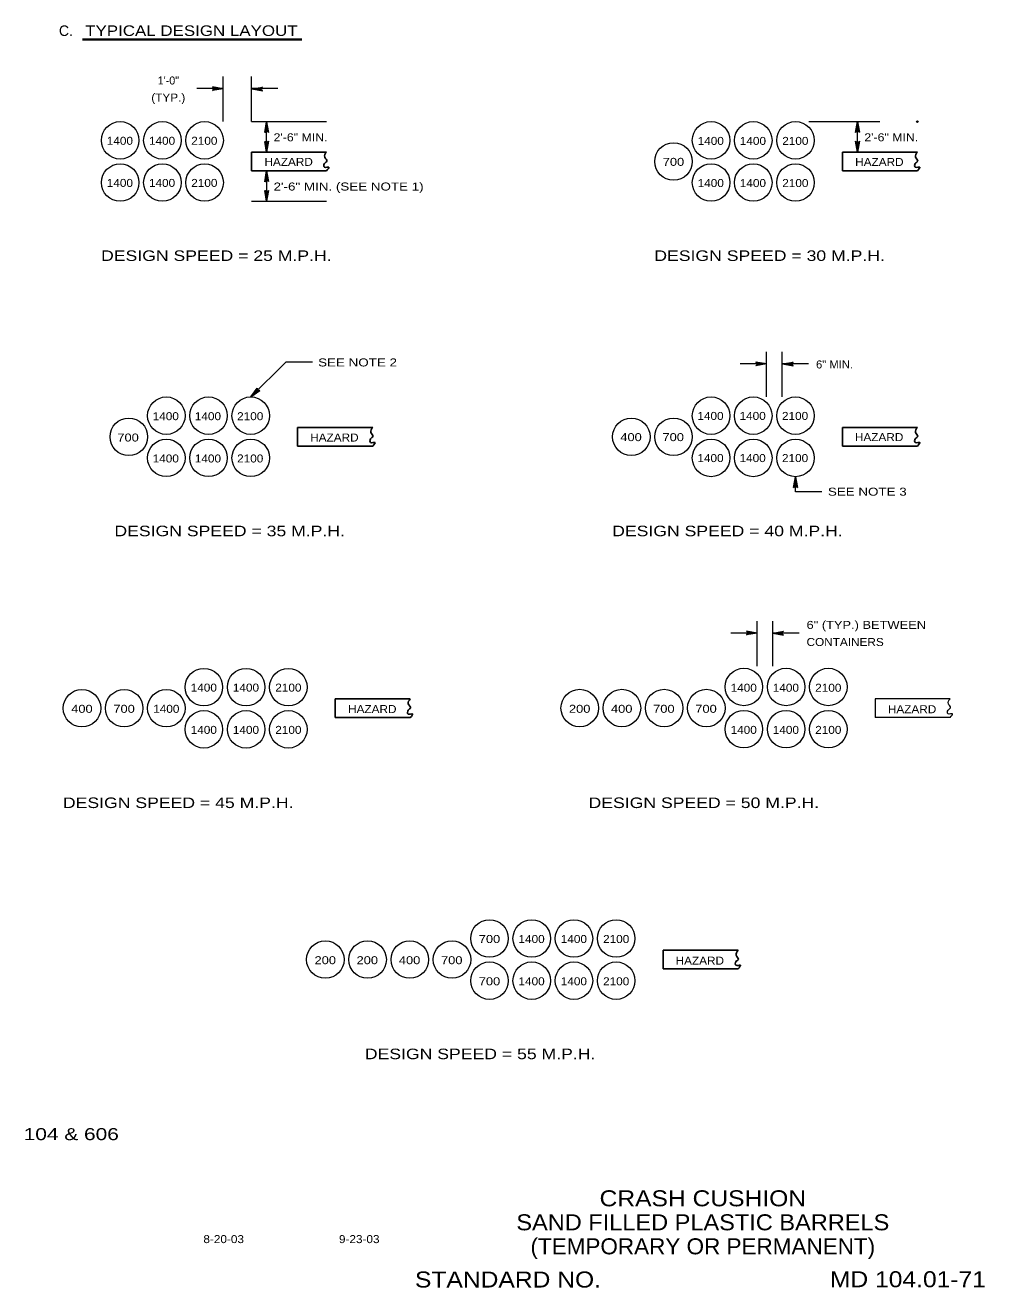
# Model space of a CAD drawing. Extents: x 2147606.19 to 2147613.38, y 2147556.61 to 2147566.08.
import ezdxf
from ezdxf.enums import TextEntityAlignment as Align

# ---------------------------------------------------------------- set-up
doc = ezdxf.new("R2010")
doc.units = 0
doc.header["$LTSCALE"] = 0.024
doc.header["$PDMODE"] = 32
doc.header["$PDSIZE"] = 0.012
for name, color, linetype, lineweight in [('1', 7, 'Continuous', 25), ('10', 7, 'Continuous', 13), ('12', 7, 'Continuous', 13)]:
    doc.layers.add(name, color=color, linetype=linetype, lineweight=lineweight)
doc.layers.add('13', color=7, linetype='Continuous')

msp = doc.modelspace()

# ---------------------------------------------------------------- hatches: boundary and pattern name
at = {"layer": '10'}
for points in [[(2147607.589, 2147565.616), (2147607.67, 2147565.601), (2147607.589, 2147565.587), (2147607.604, 2147565.601)], [(2147607.964, 2147565.586), (2147607.883, 2147565.601), (2147607.964, 2147565.614), (2147607.947, 2147565.601)], [(2147607.981, 2147565.273), (2147607.995, 2147565.354), (2147608.009, 2147565.274), (2147607.995, 2147565.288)], [(2147612.41, 2147565.274), (2147612.424, 2147565.355), (2147612.438, 2147565.275), (2147612.424, 2147565.289)], [(2147608.01, 2147565.207), (2147607.995, 2147565.126), (2147607.982, 2147565.206), (2147607.995, 2147565.191)], [(2147612.438, 2147565.208), (2147612.424, 2147565.126), (2147612.41, 2147565.207), (2147612.424, 2147565.192)], [(2147607.981, 2147564.904), (2147607.995, 2147564.985), (2147608.009, 2147564.905), (2147607.995, 2147564.92)], [(2147608.01, 2147564.838), (2147607.995, 2147564.757), (2147607.982, 2147564.837), (2147607.995, 2147564.822)], [(2147611.661, 2147563.552), (2147611.742, 2147563.538), (2147611.661, 2147563.524), (2147611.676, 2147563.538)], [(2147611.941, 2147563.523), (2147611.86, 2147563.538), (2147611.941, 2147563.552), (2147611.924, 2147563.538)], [(2147607.944, 2147563.338), (2147607.876, 2147563.29), (2147607.924, 2147563.357), (2147607.923, 2147563.337)], [(2147611.945, 2147562.611), (2147611.96, 2147562.692), (2147611.973, 2147562.611), (2147611.96, 2147562.625)], [(2147611.591, 2147561.534), (2147611.672, 2147561.519), (2147611.591, 2147561.506), (2147611.606, 2147561.519)], [(2147611.87, 2147561.504), (2147611.79, 2147561.519), (2147611.87, 2147561.533), (2147611.854, 2147561.519)]]:
    msp.add_hatch(color=256, dxfattribs=at).paths.add_polyline_path(points)

# ---------------------------------------------------------------- linework, layer by layer
at = {"layer": '1'}
for p, q in [((2147608.444, 2147565.126), (2147607.882, 2147565.126)), ((2147607.882, 2147565.126), (2147607.882, 2147564.986)), ((2147612.873, 2147565.126), (2147612.311, 2147565.126)), ((2147612.311, 2147565.126), (2147612.311, 2147564.986)), ((2147608.444, 2147564.986), (2147607.882, 2147564.986)), ((2147612.873, 2147564.986), (2147612.311, 2147564.986)), ((2147608.79, 2147563.062), (2147608.227, 2147563.062)), ((2147608.227, 2147563.062), (2147608.227, 2147562.921)), ((2147612.873, 2147563.062), (2147612.311, 2147563.062)), ((2147612.311, 2147563.062), (2147612.311, 2147562.921)), ((2147608.79, 2147562.921), (2147608.227, 2147562.921)), ((2147612.873, 2147562.921), (2147612.311, 2147562.921)), ((2147609.072, 2147561.027), (2147608.509, 2147561.027)), ((2147608.509, 2147561.027), (2147608.509, 2147560.886)), ((2147609.072, 2147560.886), (2147608.509, 2147560.886)), ((2147611.529, 2147559.142), (2147610.967, 2147559.142)), ((2147610.967, 2147559.142), (2147610.967, 2147559.002)), ((2147611.529, 2147559.002), (2147610.967, 2147559.002))]:
    msp.add_line(p, q, dxfattribs=at)
for points in [[(2147608.444, 2147564.986), (2147608.461, 2147565.013), (2147608.428, 2147565.013), (2147608.428, 2147565.041), (2147608.446, 2147565.058), (2147608.43, 2147565.089), (2147608.444, 2147565.126)], [(2147612.873, 2147564.986), (2147612.89, 2147565.013), (2147612.857, 2147565.013), (2147612.857, 2147565.041), (2147612.875, 2147565.058), (2147612.859, 2147565.089), (2147612.873, 2147565.126)], [(2147608.79, 2147562.921), (2147608.807, 2147562.949), (2147608.774, 2147562.949), (2147608.774, 2147562.976), (2147608.792, 2147562.994), (2147608.776, 2147563.024), (2147608.79, 2147563.062)], [(2147612.873, 2147562.921), (2147612.89, 2147562.949), (2147612.857, 2147562.949), (2147612.857, 2147562.976), (2147612.875, 2147562.994), (2147612.859, 2147563.024), (2147612.873, 2147563.062)], [(2147609.072, 2147560.886), (2147609.089, 2147560.913), (2147609.056, 2147560.913), (2147609.056, 2147560.941), (2147609.074, 2147560.959), (2147609.057, 2147560.989), (2147609.072, 2147561.027)], [(2147611.529, 2147559.002), (2147611.546, 2147559.029), (2147611.513, 2147559.029), (2147611.513, 2147559.056), (2147611.531, 2147559.074), (2147611.515, 2147559.104), (2147611.529, 2147559.142)]]:
    msp.add_spline(points, degree=3, dxfattribs=at)
at = {"layer": '10'}
for p, q in [((2147607.67, 2147565.355), (2147607.67, 2147565.692)), ((2147607.882, 2147565.355), (2147607.882, 2147565.692)), ((2147607.67, 2147565.602), (2147607.473, 2147565.602)), ((2147607.67, 2147565.601), (2147607.589, 2147565.616)), ((2147607.67, 2147565.601), (2147607.589, 2147565.587)), ((2147608.079, 2147565.603), (2147607.882, 2147565.603)), ((2147607.883, 2147565.601), (2147607.964, 2147565.614)), ((2147607.883, 2147565.601), (2147607.964, 2147565.586)), ((2147607.882, 2147565.355), (2147608.444, 2147565.355)), ((2147607.995, 2147565.354), (2147607.981, 2147565.273)), ((2147607.994, 2147565.126), (2147607.994, 2147565.355)), ((2147607.995, 2147565.354), (2147608.009, 2147565.274)), ((2147611.959, 2147565.355), (2147611.96, 2147565.355)), ((2147612.059, 2147565.355), (2147612.592, 2147565.355)), ((2147612.424, 2147565.355), (2147612.41, 2147565.274)), ((2147612.424, 2147565.355), (2147612.438, 2147565.275)), ((2147612.424, 2147565.127), (2147612.424, 2147565.355)), ((2147607.995, 2147565.126), (2147607.982, 2147565.206)), ((2147607.995, 2147565.126), (2147608.01, 2147565.207)), ((2147612.424, 2147565.126), (2147612.41, 2147565.207)), ((2147612.424, 2147565.126), (2147612.438, 2147565.208)), ((2147607.995, 2147564.985), (2147607.981, 2147564.904)), ((2147607.994, 2147564.986), (2147607.994, 2147564.757)), ((2147607.995, 2147564.985), (2147608.009, 2147564.905)), ((2147607.995, 2147564.757), (2147607.982, 2147564.837)), ((2147607.995, 2147564.757), (2147608.01, 2147564.838)), ((2147607.882, 2147564.757), (2147608.444, 2147564.757)), ((2147611.742, 2147563.29), (2147611.742, 2147563.628)), ((2147611.86, 2147563.29), (2147611.86, 2147563.628)), ((2147608.139, 2147563.552), (2147607.877, 2147563.29)), ((2147608.338, 2147563.552), (2147608.139, 2147563.552)), ((2147611.742, 2147563.538), (2147611.545, 2147563.538)), ((2147611.742, 2147563.538), (2147611.661, 2147563.552)), ((2147611.742, 2147563.538), (2147611.661, 2147563.524)), ((2147611.86, 2147563.538), (2147611.941, 2147563.552)), ((2147611.86, 2147563.538), (2147611.941, 2147563.523)), ((2147612.057, 2147563.538), (2147611.86, 2147563.538)), ((2147607.876, 2147563.29), (2147607.924, 2147563.357)), ((2147607.876, 2147563.29), (2147607.944, 2147563.338)), ((2147611.96, 2147562.692), (2147611.945, 2147562.611)), ((2147611.959, 2147562.58), (2147611.959, 2147562.693)), ((2147611.96, 2147562.692), (2147611.973, 2147562.611)), ((2147612.157, 2147562.58), (2147611.96, 2147562.58)), ((2147611.672, 2147561.272), (2147611.672, 2147561.609)), ((2147611.789, 2147561.272), (2147611.789, 2147561.609)), ((2147611.672, 2147561.519), (2147611.474, 2147561.519)), ((2147611.672, 2147561.519), (2147611.591, 2147561.534)), ((2147611.672, 2147561.519), (2147611.591, 2147561.506)), ((2147611.79, 2147561.519), (2147611.87, 2147561.533)), ((2147611.79, 2147561.519), (2147611.87, 2147561.504)), ((2147611.987, 2147561.519), (2147611.79, 2147561.519))]:
    msp.add_line(p, q, dxfattribs=at)
for points in [[(2147607.589, 2147565.616), (2147607.604, 2147565.601), (2147607.589, 2147565.587)], [(2147607.964, 2147565.586), (2147607.947, 2147565.601), (2147607.964, 2147565.614)], [(2147607.981, 2147565.273), (2147607.995, 2147565.288), (2147608.009, 2147565.274)], [(2147612.41, 2147565.274), (2147612.424, 2147565.289), (2147612.438, 2147565.275)], [(2147608.01, 2147565.207), (2147607.995, 2147565.191), (2147607.982, 2147565.206)], [(2147612.438, 2147565.208), (2147612.424, 2147565.192), (2147612.41, 2147565.207)], [(2147607.981, 2147564.904), (2147607.995, 2147564.92), (2147608.009, 2147564.905)], [(2147608.01, 2147564.838), (2147607.995, 2147564.822), (2147607.982, 2147564.837)], [(2147611.661, 2147563.552), (2147611.676, 2147563.538), (2147611.661, 2147563.524)], [(2147611.941, 2147563.523), (2147611.924, 2147563.538), (2147611.941, 2147563.552)], [(2147607.944, 2147563.338), (2147607.923, 2147563.337), (2147607.924, 2147563.357)], [(2147611.945, 2147562.611), (2147611.96, 2147562.625), (2147611.973, 2147562.611)], [(2147611.591, 2147561.534), (2147611.606, 2147561.519), (2147611.591, 2147561.506)], [(2147611.87, 2147561.504), (2147611.854, 2147561.519), (2147611.87, 2147561.533)]]:
    msp.add_lwpolyline(points, dxfattribs=at)
for points in [[(2147607.589, 2147565.616), (2147607.67, 2147565.601), (2147607.589, 2147565.587), (2147607.604, 2147565.601)], [(2147607.964, 2147565.586), (2147607.883, 2147565.601), (2147607.964, 2147565.614), (2147607.947, 2147565.601)], [(2147607.981, 2147565.273), (2147607.995, 2147565.354), (2147608.009, 2147565.274), (2147607.995, 2147565.288)], [(2147612.41, 2147565.274), (2147612.424, 2147565.355), (2147612.438, 2147565.275), (2147612.424, 2147565.289)], [(2147608.01, 2147565.207), (2147607.995, 2147565.126), (2147607.982, 2147565.206), (2147607.995, 2147565.191)], [(2147612.438, 2147565.208), (2147612.424, 2147565.126), (2147612.41, 2147565.207), (2147612.424, 2147565.192)], [(2147607.981, 2147564.904), (2147607.995, 2147564.985), (2147608.009, 2147564.905), (2147607.995, 2147564.92)], [(2147608.01, 2147564.838), (2147607.995, 2147564.757), (2147607.982, 2147564.837), (2147607.995, 2147564.822)], [(2147611.661, 2147563.552), (2147611.742, 2147563.538), (2147611.661, 2147563.524), (2147611.676, 2147563.538)], [(2147611.941, 2147563.523), (2147611.86, 2147563.538), (2147611.941, 2147563.552), (2147611.924, 2147563.538)], [(2147607.944, 2147563.338), (2147607.876, 2147563.29), (2147607.924, 2147563.357), (2147607.923, 2147563.337)], [(2147611.945, 2147562.611), (2147611.96, 2147562.692), (2147611.973, 2147562.611), (2147611.96, 2147562.625)], [(2147611.591, 2147561.534), (2147611.672, 2147561.519), (2147611.591, 2147561.506), (2147611.606, 2147561.519)], [(2147611.87, 2147561.504), (2147611.79, 2147561.519), (2147611.87, 2147561.533), (2147611.854, 2147561.519)]]:
    msp.add_lwpolyline(points, close=True, dxfattribs=at)
for centre in [(2147606.89724, 2147565.2142), (2147607.21365, 2147565.2142), (2147607.53005, 2147565.2142), (2147611.32637, 2147565.2142), (2147611.64277, 2147565.2142), (2147611.95918, 2147565.2142), (2147611.04512, 2147565.05597), (2147606.89724, 2147564.89774), (2147607.21365, 2147564.89774), (2147607.53005, 2147564.89774), (2147611.32637, 2147564.89774), (2147611.64277, 2147564.89774), (2147611.95918, 2147564.89774), (2147607.24309, 2147563.14981), (2147607.5595, 2147563.14981), (2147607.8759, 2147563.14981), (2147611.32637, 2147563.14965), (2147611.64277, 2147563.14965), (2147611.95918, 2147563.14965), (2147606.96184, 2147562.99158), (2147610.72871, 2147562.99142), (2147611.04512, 2147562.99142), (2147607.24309, 2147562.83335), (2147607.5595, 2147562.83335), (2147607.8759, 2147562.83335), (2147611.32637, 2147562.83318), (2147611.64277, 2147562.83318), (2147611.95918, 2147562.83318), (2147607.52478, 2147561.11456), (2147607.84119, 2147561.11456), (2147608.15759, 2147561.11456), (2147611.57236, 2147561.11592), (2147611.88877, 2147561.11592), (2147612.20517, 2147561.11592), (2147610.34189, 2147560.95769), (2147610.6583, 2147560.95769), (2147610.9747, 2147560.95769), (2147611.29111, 2147560.95769), (2147606.61072, 2147560.95633), (2147606.92712, 2147560.95633), (2147607.24353, 2147560.95633), (2147607.52478, 2147560.7981), (2147607.84119, 2147560.7981), (2147608.15759, 2147560.7981), (2147611.57236, 2147560.79946), (2147611.88877, 2147560.79946), (2147612.20517, 2147560.79946), (2147609.66575, 2147559.23014), (2147609.98215, 2147559.23014), (2147610.29856, 2147559.23014), (2147610.61496, 2147559.23014), (2147608.43528, 2147559.07191), (2147608.75168, 2147559.07191), (2147609.06809, 2147559.07191), (2147609.3845, 2147559.07191), (2147609.66575, 2147558.91368), (2147609.98215, 2147558.91368), (2147610.29856, 2147558.91368), (2147610.61496, 2147558.91368)]:
    msp.add_circle(centre, 0.14062, dxfattribs=at)
msp.add_point((2147612.873, 2147565.355), dxfattribs=at)
at = {"layer": '12', "lineweight": 35}
msp.add_line((2147606.614, 2147565.971), (2147608.26, 2147565.971), dxfattribs=at)
at = {"layer": '12'}
for p, q in [((2147613.119, 2147561.028), (2147612.557, 2147561.028)), ((2147612.557, 2147561.028), (2147612.557, 2147560.887)), ((2147613.119, 2147560.887), (2147612.557, 2147560.887))]:
    msp.add_line(p, q, dxfattribs=at)
msp.add_spline([(2147613.119, 2147560.887), (2147613.136, 2147560.915), (2147613.103, 2147560.915), (2147613.103, 2147560.942), (2147613.121, 2147560.96), (2147613.105, 2147560.99), (2147613.119, 2147561.028)], degree=3, dxfattribs=at)

# ---------------------------------------------------------------- texts
at = {"layer": '1', "width": 1.1}
for s, p in [('8-20-03', (2147607.521, 2147556.946)), ('9-23-03', (2147608.537, 2147556.946))]:
    msp.add_text(s, height=0.06, dxfattribs=at).set_placement(p)
at = {"layer": '12'}
msp.add_text('C.', height=0.07876, dxfattribs=at).set_placement((2147606.438, 2147565.997))
for s, height, width, p in [('TYPICAL DESIGN LAYOUT', 0.079, 1.2, (2147606.635, 2147565.997)), ('2\'-6" MIN.', 0.06, 1.15, (2147608.047, 2147565.207)), ('2\'-6" MIN.', 0.06, 1.15, (2147612.475, 2147565.207)), ('2\'-6" MIN. (SEE NOTE 1)', 0.06, 1.25, (2147608.047, 2147564.838)), ('DESIGN SPEED = 25 M.P.H.', 0.079, 1.25, (2147606.754, 2147564.31)), ('DESIGN SPEED = 30 M.P.H.', 0.079, 1.25, (2147610.901, 2147564.31)), ('SEE NOTE 2', 0.06, 1.25, (2147608.381, 2147563.519)), ('6" MIN.', 0.06, 1.05, (2147612.113, 2147563.504)), ('SEE NOTE 3', 0.06, 1.25, (2147612.202, 2147562.55)), ('DESIGN SPEED = 35 M.P.H.', 0.079, 1.25, (2147606.854, 2147562.246)), ('DESIGN SPEED = 40 M.P.H.', 0.079, 1.25, (2147610.585, 2147562.246)), ('6" (TYP.) BETWEEN', 0.06, 1.2, (2147612.042, 2147561.551)), ('CONTAINERS', 0.06, 1.1, (2147612.042, 2147561.423)), ('DESIGN SPEED = 45 M.P.H.', 0.079, 1.25, (2147606.468, 2147560.208)), ('DESIGN SPEED = 50 M.P.H.', 0.079, 1.25, (2147610.408, 2147560.208)), ('DESIGN SPEED = 55 M.P.H.', 0.079, 1.25, (2147608.731, 2147558.325))]:
    msp.add_text(s, height=height, dxfattribs=dict(at, width=width)).set_placement(p)
msp.add_text('1\'-0"', height=0.06, dxfattribs=at).set_placement((2147607.2585, 2147565.633), align=Align.CENTER)
for s, width, p in [('(TYP.)', 1.1, (2147607.258, 2147565.505)), ('1400', 1.1, (2147606.895, 2147565.181)), ('1400', 1.1, (2147607.211, 2147565.181)), ('2100', 1.1, (2147607.528, 2147565.181)), ('1400', 1.1, (2147611.324, 2147565.18)), ('1400', 1.1, (2147611.64, 2147565.18)), ('2100', 1.1, (2147611.958, 2147565.18)), ('HAZARD', 1.1, (2147608.16, 2147565.023)), ('700', 1.2, (2147611.0445, 2147565.023)), ('HAZARD', 1.1, (2147612.588, 2147565.022)), ('1400', 1.1, (2147606.895, 2147564.865)), ('1400', 1.1, (2147607.211, 2147564.865)), ('2100', 1.1, (2147607.528, 2147564.865)), ('1400', 1.1, (2147611.324, 2147564.864)), ('1400', 1.1, (2147611.64, 2147564.864)), ('2100', 1.1, (2147611.958, 2147564.864)), ('1400', 1.1, (2147607.239, 2147563.116)), ('1400', 1.1, (2147607.555, 2147563.116)), ('2100', 1.1, (2147607.872, 2147563.116)), ('1400', 1.1, (2147611.322, 2147563.118)), ('1400', 1.1, (2147611.638, 2147563.118)), ('2100', 1.1, (2147611.956, 2147563.118)), ('700', 1.2, (2147606.9565, 2147562.956)), ('HAZARD', 1.1, (2147608.503, 2147562.956)), ('400', 1.2, (2147610.7265, 2147562.959)), ('700', 1.2, (2147611.0425, 2147562.959)), ('HAZARD', 1.1, (2147612.586, 2147562.959)), ('1400', 1.1, (2147607.239, 2147562.799)), ('1400', 1.1, (2147607.555, 2147562.799)), ('2100', 1.1, (2147607.872, 2147562.799)), ('1400', 1.1, (2147611.322, 2147562.802)), ('1400', 1.1, (2147611.638, 2147562.802)), ('2100', 1.1, (2147611.956, 2147562.802)), ('1400', 1.1, (2147607.524, 2147561.081)), ('1400', 1.1, (2147607.84, 2147561.081)), ('2100', 1.1, (2147608.158, 2147561.081)), ('1400', 1.1, (2147611.571, 2147561.08)), ('1400', 1.1, (2147611.887, 2147561.08)), ('2100', 1.1, (2147612.205, 2147561.08)), ('400', 1.2, (2147606.6105, 2147560.922)), ('700', 1.2, (2147606.9265, 2147560.922)), ('1400', 1.1, (2147607.243, 2147560.922)), ('HAZARD', 1.1, (2147608.787, 2147560.92)), ('200', 1.2, (2147610.3415, 2147560.922)), ('400', 1.2, (2147610.6565, 2147560.922)), ('700', 1.2, (2147610.9725, 2147560.922)), ('700', 1.2, (2147611.2885, 2147560.922)), ('HAZARD', 1.1, (2147612.833, 2147560.919)), ('1400', 1.1, (2147607.524, 2147560.764)), ('1400', 1.1, (2147607.84, 2147560.764)), ('2100', 1.1, (2147608.158, 2147560.764)), ('1400', 1.1, (2147611.571, 2147560.764)), ('1400', 1.1, (2147611.887, 2147560.764)), ('2100', 1.1, (2147612.205, 2147560.764)), ('700', 1.2, (2147609.6655, 2147559.196)), ('1400', 1.1, (2147609.981, 2147559.196)), ('1400', 1.1, (2147610.298, 2147559.196)), ('2100', 1.1, (2147610.615, 2147559.196)), ('200', 1.2, (2147608.4345, 2147559.037)), ('200', 1.2, (2147608.7495, 2147559.037)), ('400', 1.2, (2147609.0665, 2147559.037)), ('700', 1.2, (2147609.3825, 2147559.037)), ('HAZARD', 1.1, (2147611.242, 2147559.034)), ('700', 1.2, (2147609.6655, 2147558.879)), ('1400', 1.1, (2147609.981, 2147558.879)), ('1400', 1.1, (2147610.298, 2147558.879)), ('2100', 1.1, (2147610.615, 2147558.879))]:
    msp.add_text(s, height=0.06, dxfattribs=dict(at, width=width)).set_placement(p, align=Align.CENTER)
at = {"layer": '13'}
for s, height, width, p in [('104 & 606', 0.09, 1.3, (2147606.5305, 2147557.718)), ('CRASH CUSHION', 0.12, 1.15, (2147611.2645, 2147557.222)), ('SAND FILLED PLASTIC BARRELS', 0.12, 1.1, (2147611.2645, 2147557.042)), ('(TEMPORARY OR PERMANENT)', 0.12, 1.05, (2147611.2645, 2147556.862)), ('STANDARD NO.', 0.12, 1.15, (2147609.804, 2147556.613)), ('MD 104.01-71', 0.12, 1.15, (2147612.802, 2147556.615))]:
    msp.add_text(s, height=height, dxfattribs=dict(at, width=width)).set_placement(p, align=Align.CENTER)

doc.saveas('drawing.dxf')
